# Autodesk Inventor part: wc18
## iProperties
Shininess: 64.0
Length Units: 11272
Angle Units: 11279
Time Units: 11290
Mass Units: 11286
Length Display Precision: 3
Angle Display Precision: 2
Compacted: True
Part Number: wc18
Document SubType Name: Modeling
Created: 2004-08
Designer: John Blackburn
Manufacturer: Standard
Standards Organization: Custom
Material: Aluminum-6061
Density: 0.0
Volumn: 0.0
Area: 0.0
PropertySet Name: Model Information
Control State: 0
Master: False
Checked Out: False
Author: John Blackburn
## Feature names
1. Base1
